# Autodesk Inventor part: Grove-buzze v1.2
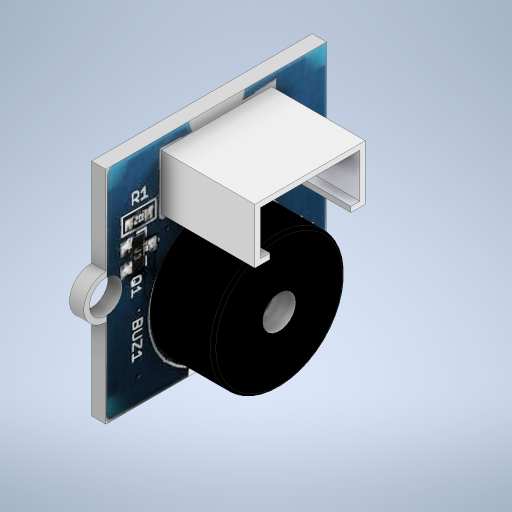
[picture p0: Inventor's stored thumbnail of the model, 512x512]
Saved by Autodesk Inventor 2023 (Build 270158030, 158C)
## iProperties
Created: 2022-12
Part Number: Grove-buzze v1.2
Material: Générique
Document SubType Name: Modeling
Designer: ecuenot
Density: 1 g/cm^3
Appearance: Par défaut
Author: ecuenot
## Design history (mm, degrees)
sketch "Esquisse1"
  geometry: L1 (20, 0)-(20, -20); L2 (0, -20)-(0, 0); L3 (11.5, 0)-(12, 0); L4 (10, 0)-(8, 0); L5 (0, 0)-(8, 0); L6 (11.5, 0)-(20, 0); L7 (20, -20)-(12, -20); L8 (8, -20)-(0, -20); C1 r 1.5 at (10, -20); A1 r 2 centre (10, 0) between (12, 0) and (8, 0); A2 r 2 centre (10, -20) between (8, -20) and (12, -20); 2 further points
  constraints: 16 end point, 5 parallel, 4 point on circle, 3 centre point, 2 coincident, 2 horizontal, 2 perpendicular, 1 horizontal alignment, 2 other
  dimensions: "d0" = 20 distance of L1.end L2.start; "d1" = 20 distance of L1.start L1.end
extrude "Extrusion1" new body sketch "Esquisse1" distance "d9" = 1.3; taper "d10" = 0 deg
sketch "Esquisse2"
  geometry: L1 (0.105, 20.104)-(20, 20); L2 (20, 20)-(19.895, -0.104); L3 (19.895, -0.104)-(0, 0); L4 (0, 0)-(0.105, 20.104); 2 further points; 1 other entity
  constraints: 2 coincident, 2 other
feature "Décalcomanie1" sketch "Esquisse2"
sketch "Esquisse3"
  geometry: L1 (-20.235, 0.241)-(-20, 20); L2 (-20, 20)-(0.235, 19.759); L3 (0.235, 19.759)-(0, 0); L4 (0, 0)-(-20.235, 0.241); 2 further points; 1 other entity
  constraints: 2 coincident, 2 other
feature "Décalcomanie2" sketch "Esquisse3"
sketch "Esquisse4"
  geometry: C1 r 6 at (10, 6.652); 1 further point
  constraints: 1 centre point
  dimensions: "d26" = 12 diameter of C1
extrude "Extrusion2" join sketch "Esquisse4" distance "d27" = 5.7; taper "d28" = 0 deg
fillet "Congé1" dims "d29" = 0.25
sketch "Esquisse5"
  geometry: C1 r 1.5 at (0, 0); 1 further point
  constraints: 1 centre point
  dimensions: "d30" = 3 diameter of C1
extrude "Extrusion3" cut sketch "Esquisse5" distance "d31" = 2; taper "d32" = 0 deg
sketch "Esquisse6"
  geometry: L1 (20, 20)-(0, 20) reference; L2 (15, 14)-(5, 14); L3 (5, 14)-(5, 19); L4 (5, 19)-(15, 19); L5 (15, 19)-(15, 14); L6 (15, 14)-(5, 19); L7 (5, 14)-(15, 19); 2 further points
  constraints: 12 end point, 2 midpoint, 2 parallel, 1 horizontal, 1 perpendicular
  dimensions: "d36" = 10 distance of L3.end L4.end; "d37" = 5 distance of L2.end L3.end
extrude "Extrusion4" join sketch "Esquisse6" distance "d38" = 8.5; taper "d39" = 0 deg
feature "Coque2" dims "d41" = 0.5
sketch "Esquisse7"
  geometry: L1 (3.749, 1.295)-(8.801, 1.295); L2 (8.801, 1.295)-(8.801, 8.634); L3 (8.801, 8.634)-(3.749, 8.634); L4 (3.749, 8.634)-(3.749, 1.295); L5 (3.749, 1.295)-(8.801, 8.634); L6 (8.801, 1.295)-(3.749, 8.634); 1 further point
  constraints: 12 end point, 2 parallel, 1 horizontal, 1 perpendicular
extrude "Extrusion5" cut sketch "Esquisse7" stored distance "d44" = 8.5; taper "d45" = 0 deg
node "Solide1"
node "Image1"
node "Image2"
